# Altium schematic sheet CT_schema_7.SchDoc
size 277 x 170 mm
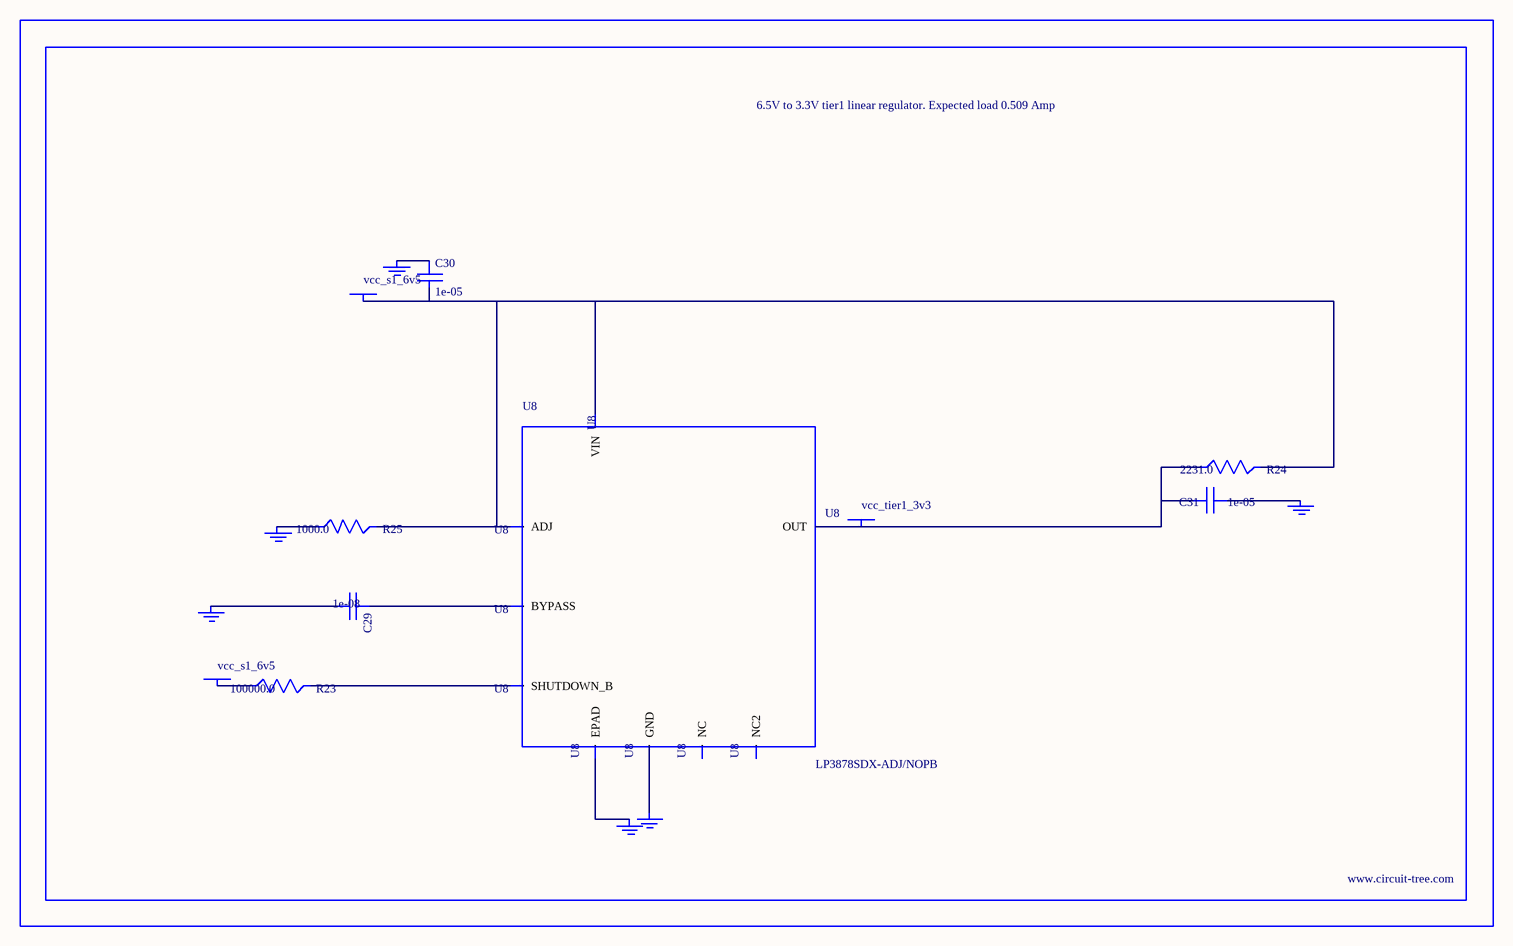
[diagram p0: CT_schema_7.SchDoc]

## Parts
BORDER6  (no value)
C29  1e-08  [C0402]
C30  1e-05  [C1206]
C31  1e-05  [C1210]
GND_INSTANCE_6_0  (no value)
GND_INSTANCE_6_1  (no value)
GND_INSTANCE_6_2  (no value)
GND_INSTANCE_6_3  (no value)
GND_INSTANCE_6_4  (no value)
GND_INSTANCE_6_5  (no value)
POWER_INSTANCE_6_0  vcc_s1_6v5
POWER_INSTANCE_6_1  vcc_s1_6v5
POWER_INSTANCE_6_2  vcc_tier1_3v3
R23  100000.0  [R0603]
R24  2231.0  [R0603]
R25  1000.0  [R0603]
U8  LP3878SDX-ADJ/NOPB  [WSON-8]

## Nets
NetC29_1: C29.1 U8.1(BYPASS)
NetC29_2: C29.2 GND_INSTANCE_6_0.0(GND)
NetC30_1: C30.1 GND_INSTANCE_6_1.0(GND)
NetC30_2: C30.2 POWER_INSTANCE_6_0.0(PWR) R24.2 R25.2 U8.4(VIN) U8.6(ADJ)
NetC31_1: C31.1 GND_INSTANCE_6_2.0(GND)
NetC31_2: C31.2 POWER_INSTANCE_6_2.0(PWR) R24.1 U8.5(OUT)
NetGND_INSTANCE_6_3_0: GND_INSTANCE_6_3.0(GND) R25.1
NetGND_INSTANCE_6_4_0: GND_INSTANCE_6_4.0(GND) U8.PAD(EPAD)
NetGND_INSTANCE_6_5_0: GND_INSTANCE_6_5.0(GND) U8.3(GND)
NetPOWER_INSTANCE_6_1_0: POWER_INSTANCE_6_1.0(PWR) R23.1
NetR23_2: R23.2 U8.8(SHUTDOWN_B)

Not connected (* = marked no-connect by the designer): U8 2(NC) 7(NC2)

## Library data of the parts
BORDER6 = BORDER_PAGE6
C29 = C0402C103K3RAC
C30 = C1206C106K3RACTU
C31 = GRM32DR61E106MA12L
GND_INSTANCE_6_0-GND_INSTANCE_6_5 = GND
POWER_INSTANCE_6_0-POWER_INSTANCE_6_2 = PWR
R23 = RC0603JR-07100KL
R24 = R24
R25 = RC0603JR-071KL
